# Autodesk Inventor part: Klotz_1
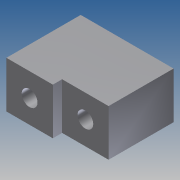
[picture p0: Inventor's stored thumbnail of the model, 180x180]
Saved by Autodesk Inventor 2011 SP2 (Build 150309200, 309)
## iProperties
Created: 2012-06
Part Number: Klotz_1
Document SubType Name: Modeling
Designer: JRE
Density: 1 g/cm^3
Author: JRE
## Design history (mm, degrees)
sketch "Skizze1"
  geometry: L1 (0, 0)-(50, 0); L2 (100, 10)-(100, 80); L3 (100, 80)-(0, 80); L4 (0, 80)-(0, 0); L5 (100, 10)-(50, 10); L6 (50, 10)-(50, 0)
  constraints: 12 end point, 2 horizontal, 2 parallel, 1 perpendicular
  dimensions: "d0" = 100 distance of L2.end L3.end; "d1" = 80 distance of L3.end L1.start; "d3" = 50 distance of L1.start L1.end; "d4" = 10 distance of L5.end L1.end; "d5" = 50 distance of L2.start L5.end
extrude "Extrusion1" new body sketch "Skizze1" distance "d6" = 50; taper "d7" = 0 deg
hole "Hole1" diameter "d10" = 17; stored, may be unused: countersink angle "d14" = 90 deg, drill point angle "d16" = 118 deg; dims "d8" = 25, "d9" = 25, "d11" = 6, "d12" = 4, "d13" = 2, "d15" = 100
hole "Hole2" diameter "d19" = 17; stored, may be unused: countersink angle "d23" = 90 deg, drill point angle "d25" = 118 deg; dims "d17" = 25, "d18" = 25, "d20" = 6, "d21" = 4, "d22" = 2, "d24" = 70
node "Volumenkörper1"
